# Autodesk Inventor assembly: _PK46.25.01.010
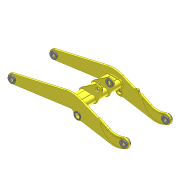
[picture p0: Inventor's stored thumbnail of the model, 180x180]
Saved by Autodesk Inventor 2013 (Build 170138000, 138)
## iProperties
Created: 2005-04
Part Number: _PK46.25.01.010
Document SubType Name: Assembly
Designer: salex
Manufacturer: Standard
Standards Organization: Custom
Description: Рама
Author: salex
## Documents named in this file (8)
- C:\Product Design Suite 2013 Test Drive\Dynamic Simulation\Workspace\Assy, Chassis, Front\PK46.25.01.010.iam
- C:\Product Design Suite 2013 Test Drive\Dynamic Simulation\Workspace\Assy, Chassis, Front\PK46.25.01.001.ipt
- C:\Product Design Suite 2013 Test Drive\Dynamic Simulation\Workspace\Assy, Chassis, Front\PK46.25.01.002.ipt
- C:\Product Design Suite 2013 Test Drive\Dynamic Simulation\Workspace\Assy, Chassis, Front\PK46.25.01.003.ipt
- C:\Product Design Suite 2013 Test Drive\Dynamic Simulation\Workspace\Assy, Chassis, Front\PK46.25.01.004.ipt
- C:\Product Design Suite 2013 Test Drive\Dynamic Simulation\Workspace\Assy, Chassis, Front\PK46.25.01.008.ipt
- C:\Product Design Suite 2013 Test Drive\Dynamic Simulation\Workspace\Assy, Chassis, Front\PK46.25.01.012.ipt
- C:\Product Design Suite 2013 Test Drive\Dynamic Simulation\Workspace\Assy, Chassis, Front\PK46.25.01.020.iam
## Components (19 placed, 7 different names)
1. PK46.25.01.001:1 — Вставка:3, Вставка:4, Вставка:7, Вставка:8, Совмещение:1, Совмещение:2, Совмещение:3, Вставка:10, Вставка:11, Угол:1
2. PK46.25.01.002:1 — Вставка:1, Вставка:2, Вставка:5, Вставка:6, Совмещение:1, Совмещение:2, Совмещение:3, Вставка:9, Вставка:12, Угол:2, Совмещение:9, Совмещение:10
3. PK46.25.01.003:1 — Вставка:3, Вставка:14
4. PK46.25.01.003:2 — Вставка:4, Вставка:16
5. PK46.25.01.003:3 — Вставка:1, Вставка:13
6. PK46.25.01.003:4 — Вставка:2, Вставка:15
7. PK46.25.01.003:5 — Вставка:5
8. PK46.25.01.003:6 — Вставка:6
9. PK46.25.01.003:7 — Вставка:7
10. PK46.25.01.003:8 — Вставка:8
11. PK46.25.01.004:1 — Вставка:10
12. PK46.25.01.004:2 — Вставка:9
13. PK46.25.01.008:1 — Вставка:11, Совмещение:6, Совмещение:7, Совмещение:8
14. PK46.25.01.008:2 — Вставка:12, Совмещение:4, Совмещение:5
15. PK46.25.01.012:1 — Вставка:15
16. PK46.25.01.012:2 — Вставка:16, Угол:1
17. PK46.25.01.012:3 — Вставка:13, Угол:2
18. PK46.25.01.012:4 — Вставка:14
19. PK46.25.01.020:1 [sub-assembly] — Совмещение:4, Совмещение:5, Совмещение:6, Совмещение:7, Совмещение:8, Совмещение:14, Flush:5, Angle:4, Mate:20, Mate:21
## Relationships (33: Insert 16, Mate 13, Angle 3, Flush 1)
- Вставка:1 [Insert]: PK46.25.01.002:1 ↔ PK46.25.01.003:3
- Вставка:2 [Insert]: PK46.25.01.002:1 ↔ PK46.25.01.003:4
- Вставка:3 [Insert]: PK46.25.01.001:1 ↔ PK46.25.01.003:1
- Вставка:4 [Insert]: PK46.25.01.001:1 ↔ PK46.25.01.003:2
- Вставка:5 [Insert]: PK46.25.01.002:1 ↔ PK46.25.01.003:5
- Вставка:6 [Insert]: PK46.25.01.002:1 ↔ PK46.25.01.003:6
- Вставка:7 [Insert]: PK46.25.01.001:1 ↔ PK46.25.01.003:7
- Вставка:8 [Insert]: PK46.25.01.001:1 ↔ PK46.25.01.003:8
- Совмещение:1 [Mate]: PK46.25.01.001:1 ↔ PK46.25.01.002:1
- Совмещение:2 [Mate]: PK46.25.01.001:1 ↔ PK46.25.01.002:1
- Совмещение:3 [Mate]: PK46.25.01.001:1 ↔ PK46.25.01.002:1
- Вставка:9 [Insert]: PK46.25.01.002:1 ↔ PK46.25.01.004:2
- Вставка:10 [Insert]: PK46.25.01.001:1 ↔ PK46.25.01.004:1
- Вставка:11 [Insert]: PK46.25.01.001:1 ↔ PK46.25.01.008:1
- Вставка:12 [Insert]: PK46.25.01.002:1 ↔ PK46.25.01.008:2
- Совмещение:4 [Mate]: PK46.25.01.008:2 ↔ PK46.25.01.020:1
- Совмещение:5 [Mate]: PK46.25.01.008:2 ↔ PK46.25.01.020:1
- Совмещение:6 [Mate]: PK46.25.01.008:1 ↔ PK46.25.01.020:1
- Совмещение:7 [Mate]: PK46.25.01.008:1 ↔ PK46.25.01.020:1
- Совмещение:8 [Mate]: PK46.25.01.008:1 ↔ PK46.25.01.020:1
- Вставка:13 [Insert]: PK46.25.01.003:3 ↔ PK46.25.01.012:3
- Вставка:14 [Insert]: PK46.25.01.003:1 ↔ PK46.25.01.012:4
- Вставка:15 [Insert]: PK46.25.01.003:4 ↔ PK46.25.01.012:1
- Вставка:16 [Insert]: PK46.25.01.003:2 ↔ PK46.25.01.012:2
- Угол:1 [Angle]: PK46.25.01.001:1 ↔ PK46.25.01.012:2
- Угол:2 [Angle]: PK46.25.01.002:1 ↔ PK46.25.01.012:3
- Совмещение:9 [Mate]: PK46.25.01.002:1
- Совмещение:10 [Mate]: PK46.25.01.002:1
- Совмещение:14 [Mate]: PK46.25.01.020:1
- Flush:5: PK46.25.01.020:1
- Angle:4: PK46.25.01.020:1
- Mate:20: PK46.25.01.020:1
- Mate:21: PK46.25.01.020:1
